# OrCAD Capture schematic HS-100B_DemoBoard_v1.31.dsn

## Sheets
1 01. Release Note: title: HS-100B Reference Circuit; rev: 1.31; company: C-MEDIA ELECTRONICS Inc.; note: Release Note; note: 6F., 100, Sec. 4, Civil Boulevard, Taipei, Taiwan, R.O.C.
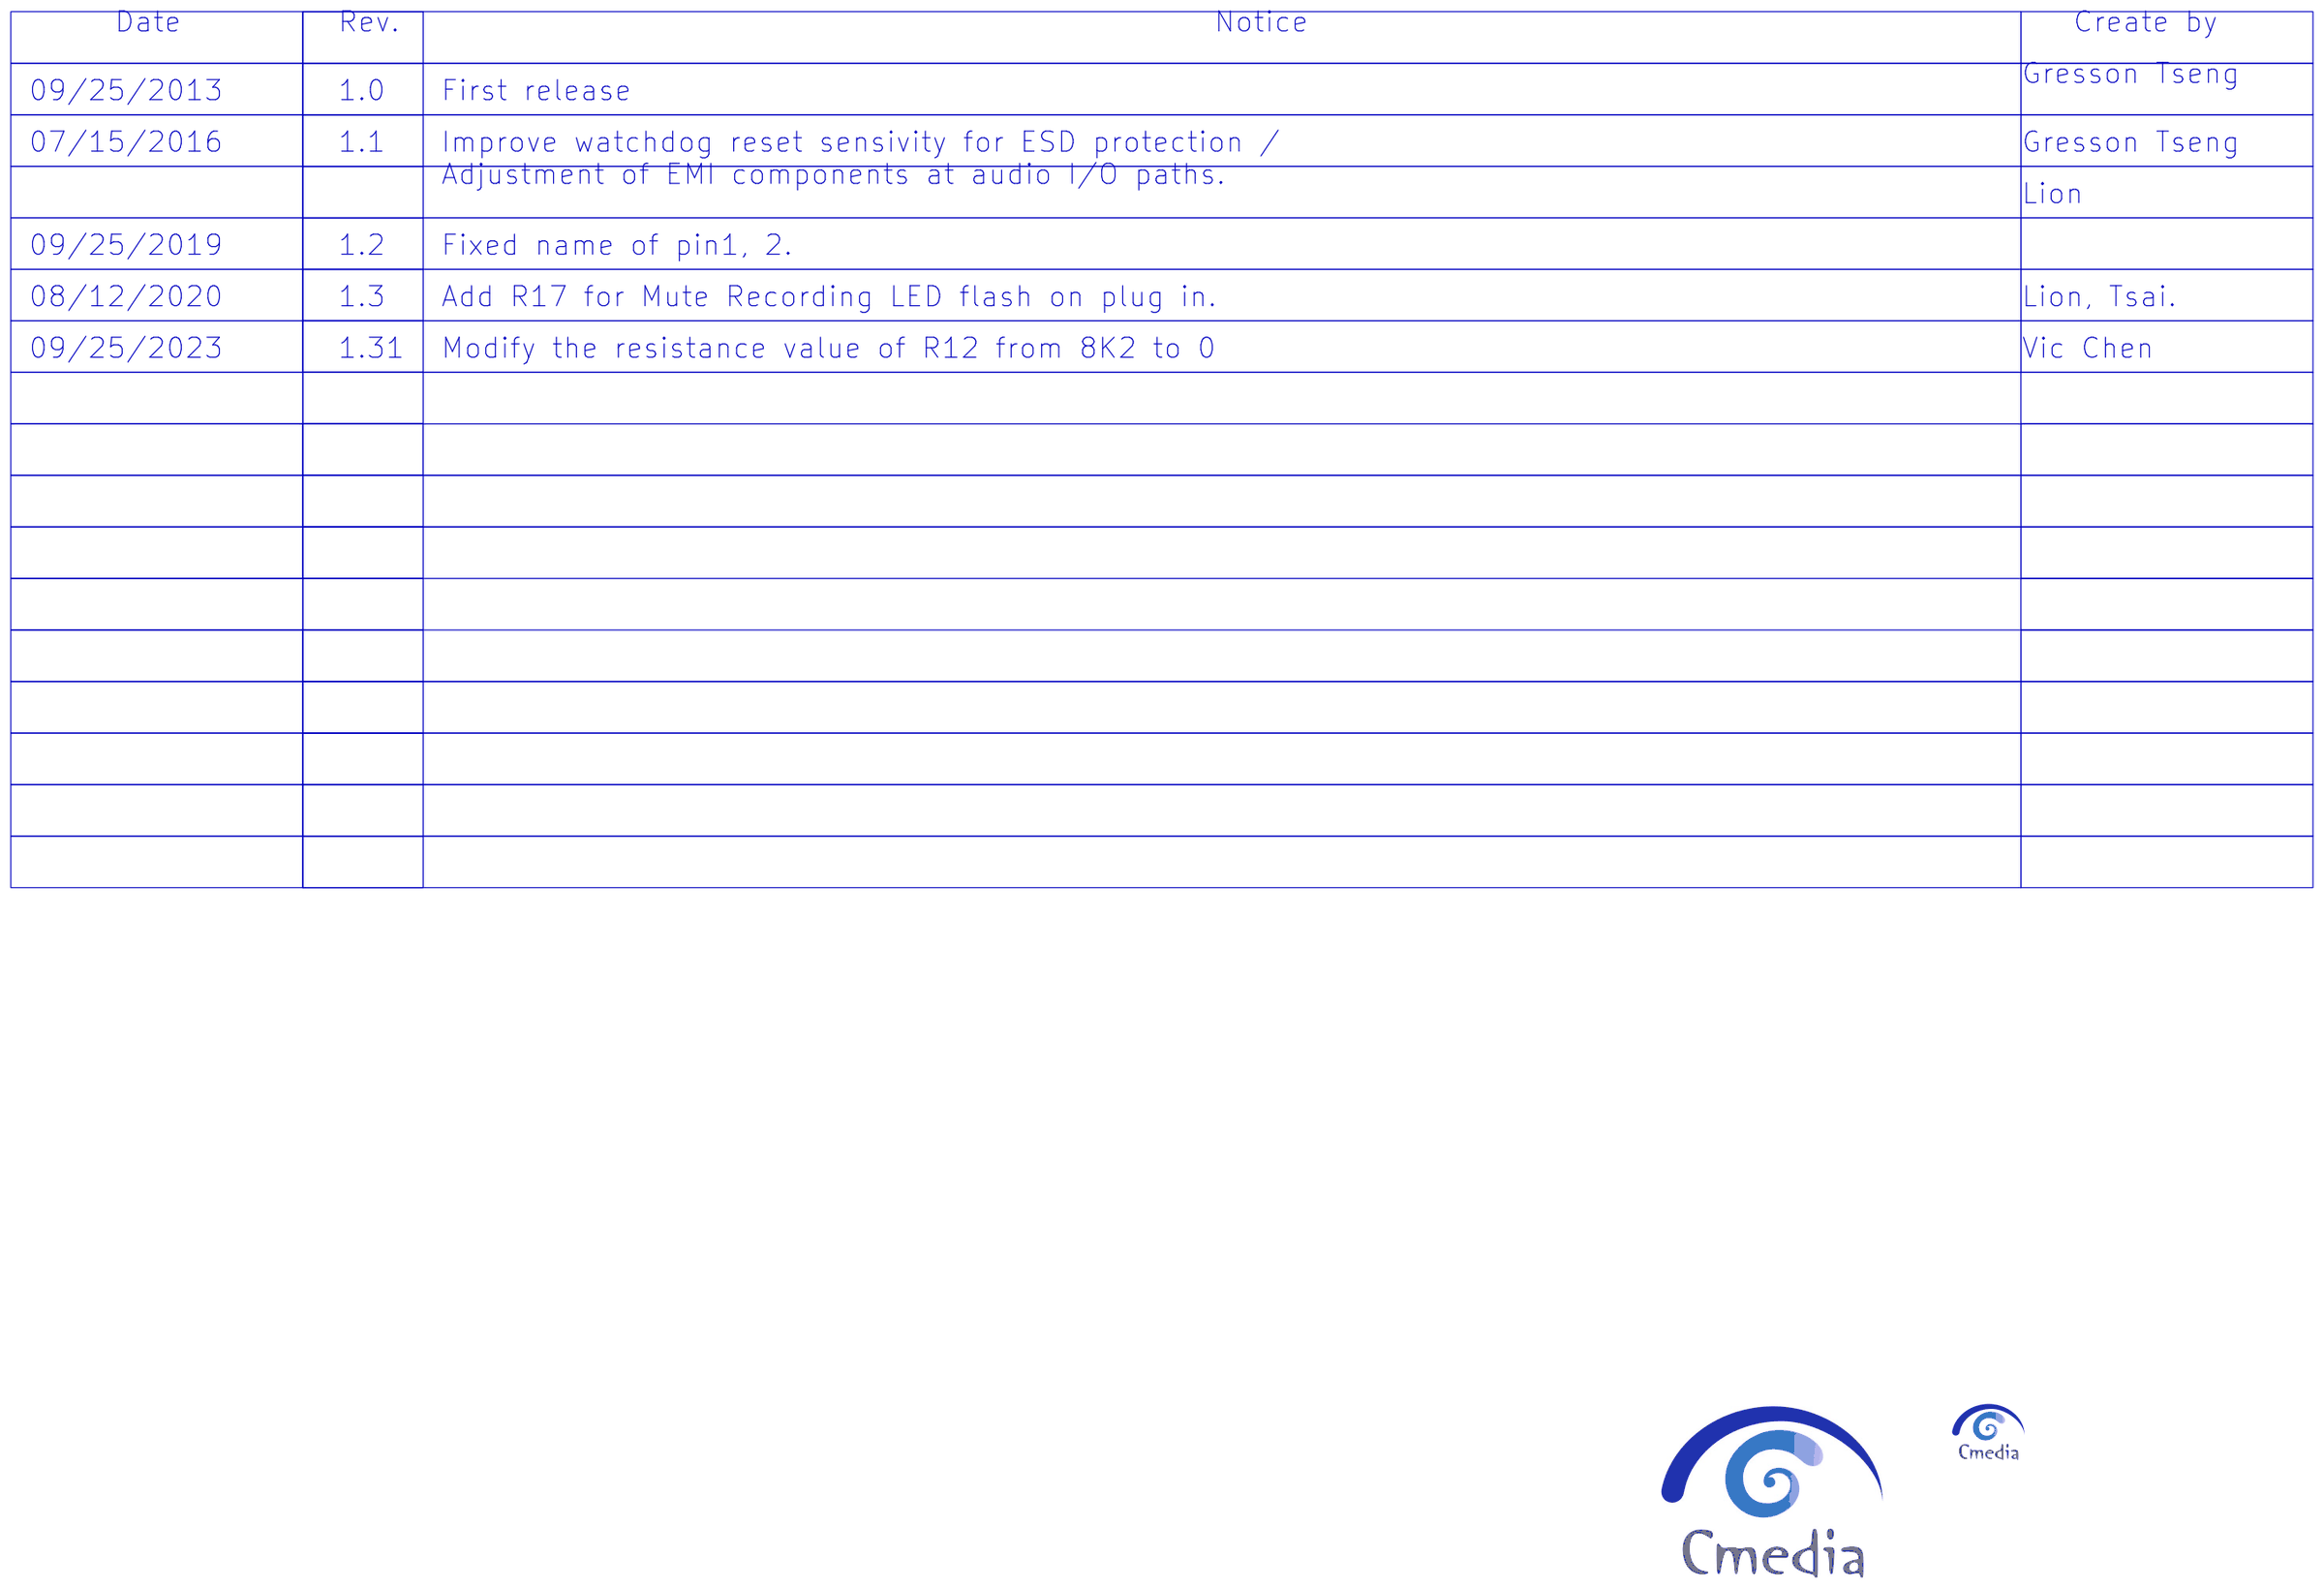
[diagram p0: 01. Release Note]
2 02. Block Diagram: note: Block Diagram
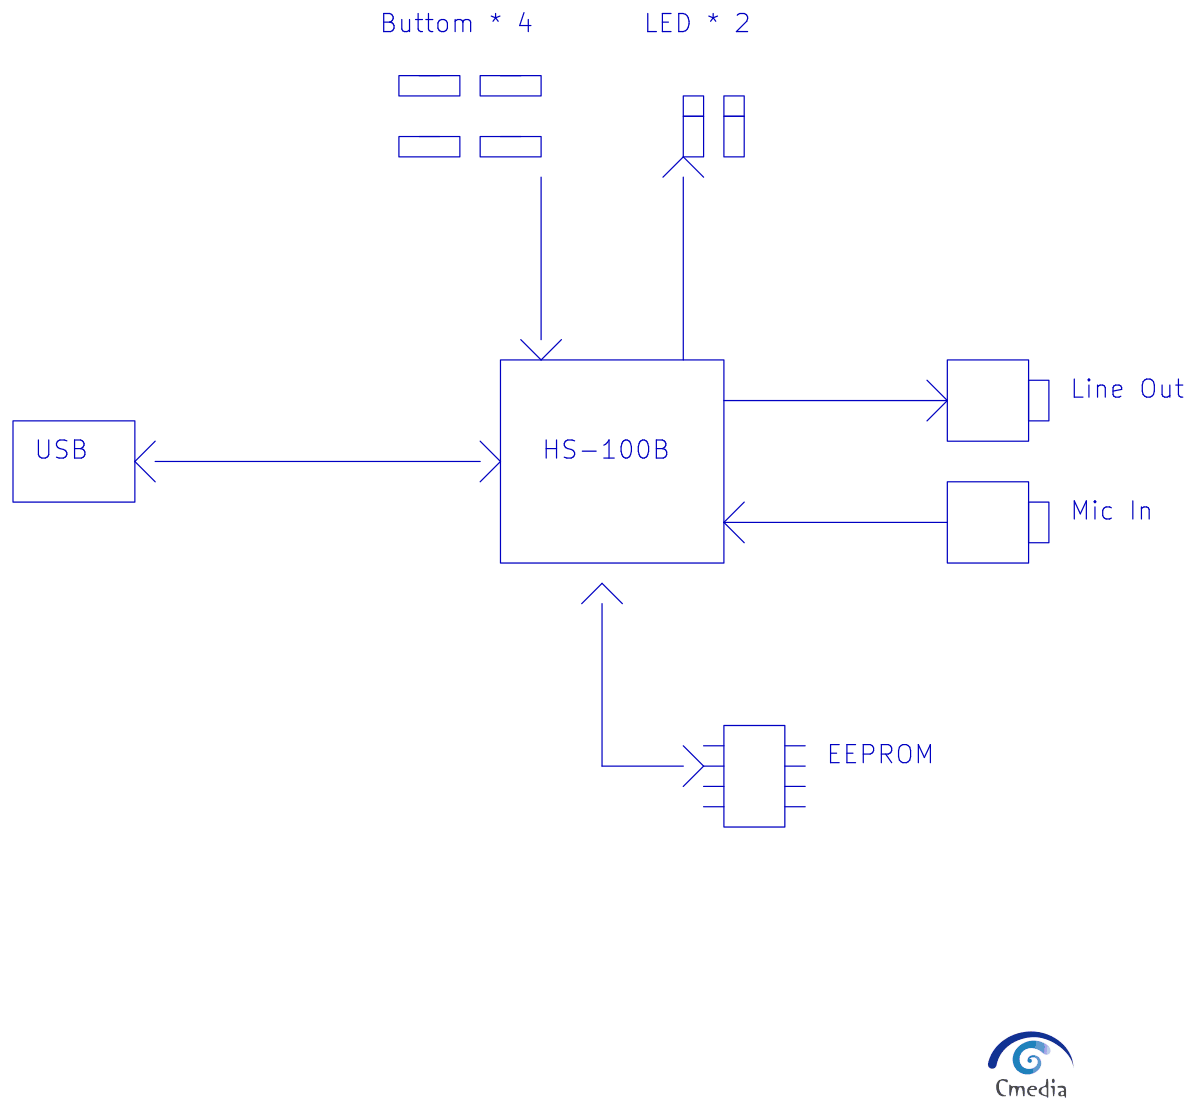
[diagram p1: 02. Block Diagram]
3 03. HS-100B: size A4; note: Schematic
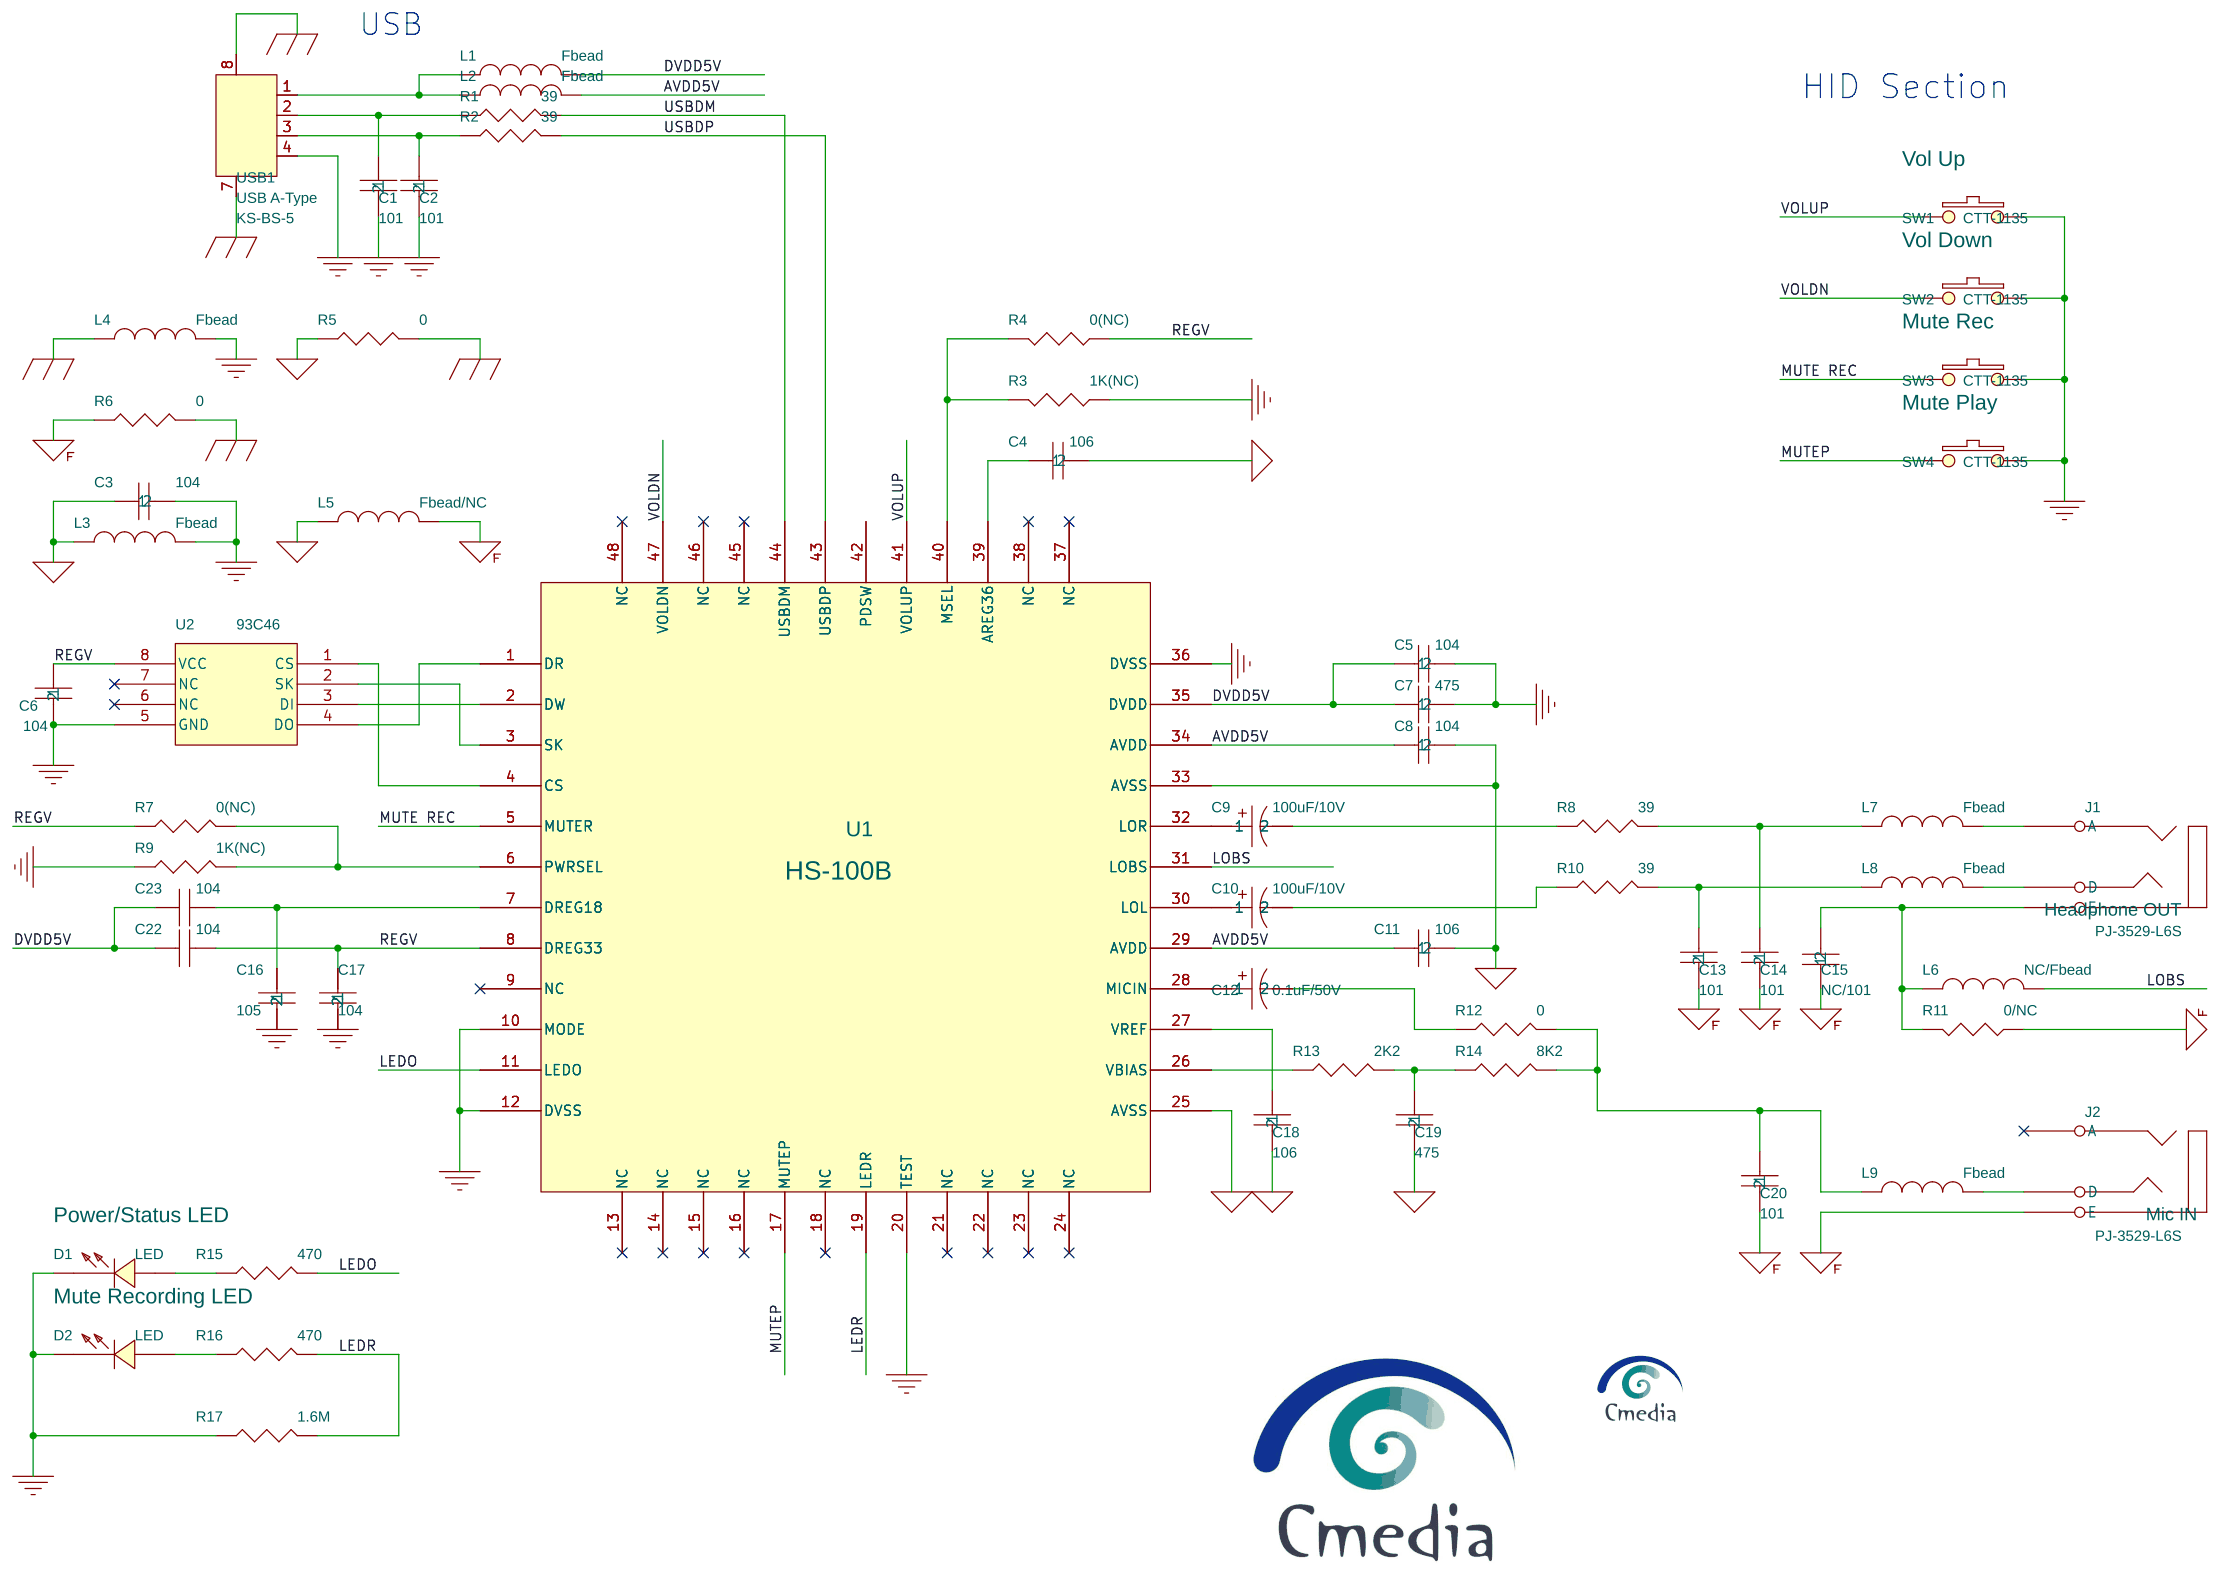
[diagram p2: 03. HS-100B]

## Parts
C1  101  [C0603]
C2  101  [C0603]
C3  104  [C0603]
C4  106  [C0603]
C5  104  [C0603]
C6  104  [C0603]
C7  475  [C0603]
C8  104  [C0603]
C9  100uF/10V  [5x7]
C10  100uF/10V  [5x7]
C11  106  [C0603]
C12  0.1uF/50V  [3216-18]
C13  101  [C0603]
C14  101  [C0603]
C15  NC/101  [C0603]
C16  105  [C0603]
C17  104  [C0603]
C18  106  [C0603]
C19  475  [C0603]
C20  101  [C0603]
C22  104
C23  104
D1  LED  [D0603]
D2  LED  [D0603]
J1  PJ-3529-L6S
J2  PJ-3529-L6S
L1  Fbead  [L0603]
L2  Fbead  [L0603]
L3  Fbead  [L0603]
L4  Fbead  [L0603]
L5  Fbead/NC  [L0603]
L6  NC/Fbead  [L0603]
L7  Fbead  [L0603]
L8  Fbead  [L0603]
L9  Fbead  [L0603]
R1  39  [R0603]
R2  39  [R0603]
R3  1K(NC)  [R0603]
R4  0(NC)  [R0603]
R5  0  [R0603]
R6  0  [R0603]
R7  0(NC)  [R0603]
R8  39  [R0603]
R9  1K(NC)  [R0603]
R10  39  [R0603]
R11  0/NC  [R0603]
R12  0  [R0603]
R13  2K2  [R0603]
R14  8K2  [R0603]
R15  470  [R0603]
R16  470  [R0603]
R17  1.6M  [R0603]
SW1  CTT-1135
SW2  CTT-1135
SW3  CTT-1135
SW4  CTT-1135
U1  HS-100B  [LQFP-48]
U2  93C46  [SOP-8]
USB1  KS-BS-5  [USB-TYPEB-SMD]

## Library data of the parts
C1 = CAP_NP_14
C2 = CAP_NP_8
C3 = CAP_NP_2
C4 = CAP_NP_4
C5 = CAP_NP_3
C6 = CAP_NP_5
C7 = CAP_NP_15
C8 = CAP_NP_7
C9 = CAP_POL
C10 = CAP_POL_2
C11 = CAP_NP_13
C12 = CAP_POL_1
C13 = CAP_NP_11
C14 = CAP_NP_6
C15 = CAP_NP
C16 = CAP_NP_1
C17 = CAP_NP_12
C18 = CAP_NP_10
C19 = CAP_NP_9
C20 = CAP_NP_16
C22 C23 = CAPACITOR_NON-POL
D1 = LED: 1ST PART FIELD: Power/Status LED
D2 = LED: 1ST PART FIELD: Mute Recording LED
J1 = PHONEJACK_STEREO_SW_1: 1ST PART FIELD: Headphone OUT
J2 = PHONEJACK_STEREO_SW_0: 1ST PART FIELD: Mic IN
L1-L9 = INDUCTOR
R1 = R_v2_15
R2 = R_v2_6
R3 = R_v2_5
R4 = R_v2_1
R5 = R_v2_8
R6 = R_v2_11
R7 = R_v2_4
R8 = R_v2_10
R9 = R_v2_9
R10 = R_v2_13
R11 = R_v2
R12 = R_v2_2
R13 = R_v2_16
R14 = R_v2_14
R15 = R_v2_7
R16 = R_v2_3
R17 = R_v2_12
SW1 = SW_TACT-SPST_SM: 1ST PART FIELD: Vol Up
SW2 = SW_TACT-SPST_SM: 1ST PART FIELD: Vol Down
SW3 = SW_TACT-SPST_SM: 1ST PART FIELD: Mute Rec
SW4 = SW_TACT-SPST_SM: 1ST PART FIELD: Mute Play
U1 = CM072_11
U2 = 93C46: 1ST PART FIELD: Option(93C46)
USB1 = HEADER_4_0: 1ST PART FIELD: USB A-Type

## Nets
AGND: C3.1 C4.2 C8.2 C11.2 C18.2 C19.2 L3.2 L5.2 R5.1 U1.25(AVSS) U1.33(AVSS)
AVDD5V: C8.1 C11.1 L2.1 U1.29(AVDD) U1.34(AVDD)
DGND: C1.2 C2.2 C3.2 C5.2 C6.2 C7.2 C16.2 C17.2 D1.2(CATHODE) D2.2(CATHODE) L3.1 L4.1 R3.1 R9.2 R17.2 SW1.2 SW2.2 SW3.2 SW4.2 U1.10(MODE) U1.12(DVSS) U1.20(TEST) U1.36(DVSS) U2.5(GND) USB1.4
DVDD5V: C5.1 C7.1 C22.1 C23.1 L1.1 U1.35(DVDD)
CGND: L4.2 R5.2 R6.2 USB1.7 USB1.8
IO_GND: C13.2 C14.2 C15.1 C20.2 J2.1(E) L5.1 R6.1 R11.1
LEDO: R15.1 U1.11(LEDO)
LEDR: R16.1 R17.1 U1.19(LEDR)
LOBS: L6.1 U1.31(LOBS)
MUTE REC: SW3.1 U1.5(MUTER)
MUTEP: SW4.1 U1.17(MUTEP)
REGV: C6.1 C17.1 C22.2 R4.1 R7.2 U1.8(DREG33) U2.8(VCC)
USBDM: R1.2 U1.44(USBDM)
USBDP: R2.2 U1.43(USBDP)
VOLDN: SW2.1 U1.47(VOLDN)
VOLUP: SW1.1 U1.41(VOLUP)
N2411747: C16.1 C23.2 U1.7(DREG18)
N2830732: C19.1 R13.2 R14.1
N2830868: R13.1 U1.26(VBIAS)
N2936350: D2.1(ANODE) R16.2
N2937689: U1.1(DR) U2.4(DO)
N2937695: U1.2(DW) U2.3(DI)
N2937701: U1.4(CS) U2.1(CS)
N2937719: U1.3(SK) U2.2(SK)
N3209864: R7.1 R9.1 U1.6(PWRSEL)
N3224534: R3.2 R4.2 U1.40(MSEL)
N3224784: C4.1 U1.39(AREG36)
N3225427: D1.1(ANODE) R15.2
N3242940: C14.1 L7.2 R8.2
N3243264: C20.1 L9.2 R12.2 R14.2
N3243268: C13.1 L8.2 R10.2
N3243284: C10.2 R10.1
N3243336: C9.2 R8.1
N3243368: C18.1 U1.27(VREF)
N16776821: C12.2 R12.1
N16957603: C15.2 J1.1(E) L6.2 R11.2
N16972509: C1.1 R1.1 USB1.2
N16972511: C2.1 R2.1 USB1.3
N16972593: L1.2 L2.2 USB1.1
N17003989: J1.3(A) L7.1
N17004756: J1.2(D) L8.1
N17006336: J2.2(D) L9.1
N17082237: C9.1 U1.32(LOR)
N17082238: C12.1 U1.28(MICIN)
N17082240: C10.1 U1.30(LOL)

Not connected (* = marked no-connect by the designer): J2 3(A)*; U1 9(NC)* 13(NC)* 14(NC)* 15(NC)* 16(NC)* 18(NC)* 21(NC)* 22(NC)* 23(NC)* 24(NC)* 37(NC)* 38(NC)* 42(PDSW) 45(NC)* 46(NC)* 48(NC)*; U2 6(NC)* 7(NC)*

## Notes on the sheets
sheet 1
- Date
- Rev.
- Notice
- Create by
- 09/25/2013
- 1.0
- First release
- Gresson Tseng
- 07/15/2016
- 1.1
- Improve watchdog reset sensivity for ESD protection /
  Adjustment of EMI components at audio I/O paths.
- Gresson Tseng
- Lion
- 09/25/2019
- 1.2
- Fixed name of pin1, 2.
- 08/12/2020
- 1.3
- Add R17 for Mute Recording LED flash on plug in.
- Lion, Tsai.
- 09/25/2023
- 1.31
- Modify the resistance value of R12 from 8K2 to 0
- Vic Chen
sheet 2
- Buttom * 4
- LED * 2
- Line Out
- USB
- HS-100B
- Mic In
- EEPROM
sheet 3
- USB
- HID Section
